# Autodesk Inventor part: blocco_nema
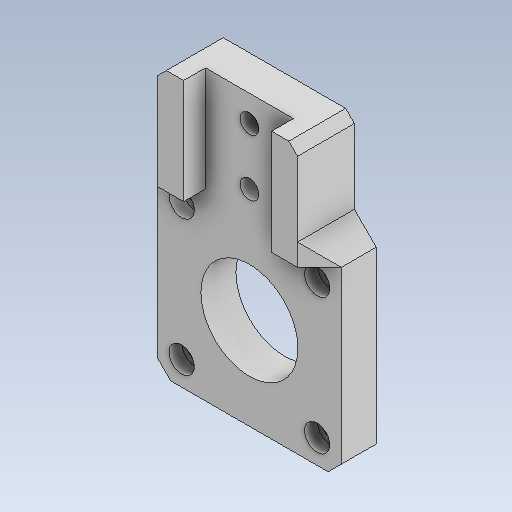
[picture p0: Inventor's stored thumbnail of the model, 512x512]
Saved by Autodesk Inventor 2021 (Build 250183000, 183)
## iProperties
Created: 2026-01
Part Number: blocco_nema
Material: Generico
Document SubType Name: Modeling
Designer: hp
Density: 1 g/cm^3
Appearance: Default
Author: hp
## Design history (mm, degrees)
feature "Solido1"
body "Solid1"
